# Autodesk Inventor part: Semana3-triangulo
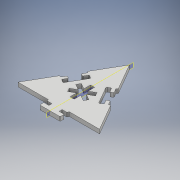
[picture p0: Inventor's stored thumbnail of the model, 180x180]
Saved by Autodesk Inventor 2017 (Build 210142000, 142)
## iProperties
Created: 2017-02
Part Number: Semana3-triangulo
Material: Generic
Document SubType Name: Modeling
Designer: diego
Density: 1 g/cm^3
Appearance: Default
Gdimension: 60.000 mm
garganta: 7.500 mm
d2: 3.750 mm
gargantah: 3.500 mm
espesor: 3.000 mm
d6: 0.00 deg
headw: 15.000 mm
headh: 3.020 mm
d36: 3.000 mm
d37: 0.00 deg
d42: 3.000 mm
d43: 0.00 deg
d44: 0.500 mm
d45: 30.00 deg
d47: 30.00 deg
d50: 15.040 mm
d51: 3.020 mm
d52: 3.000 ul
d54: 360.00 deg
d56: 3.000 mm
d57: 0.00 deg
d63: 90.00 deg
Author: diego
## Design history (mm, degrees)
sketch "Sketch1"
  geometry: L1 (0, 34.641)-(-30, -17.321); L2 (-30, -17.321)-(30, -17.321); L3 (30, -17.321)-(0, 34.641); L4 (-3.75, -17.321)-(-3.75, -20.821); L5 (3.75, -17.321)-(3.75, -20.821); L6 (-3.75, -20.821)-(-7.5, -20.821); L7 (-7.5, -20.821)-(-7.5, -23.841); L8 (-7.5, -23.841)-(7.5, -23.841); L9 (7.5, -23.841)-(7.5, -20.821); L10 (7.5, -20.821)-(3.75, -20.821); L11 (-3.75, -17.321)-(-3.75, -13.821); L12 (3.75, -17.321)-(3.75, -13.821); L13 (-3.75, -13.821)-(-7.5, -13.821); L14 (-7.5, -13.821)-(-7.5, -10.801); L15 (-7.5, -10.801)-(7.5, -10.801); L16 (7.5, -10.801)-(7.5, -13.821); L17 (7.5, -13.821)-(3.75, -13.821); L18 (-30, -17.321)-(15, 8.66); L19 (30, -17.321)-(-15, 8.66); L20 (0, 34.641)-(0, -17.321); L21 (3.75, -17.321)-(-3.75, -17.321); L22 (-7.5, -17.321)-(7.5, -17.321); L23 (7.5, -17.321)-(7.5, -18.571); L24 (7.5, -18.571)-(-7.5, -18.571); L25 (-7.5, -18.571)-(-7.5, -17.321); L26 (-7.5, -16.071)-(-7.5, -17.321); L27 (7.5, -16.071)-(-7.5, -16.071); L28 (7.5, -17.321)-(7.5, -16.071); L29 (17.667, 1.54)-(18.75, 2.165); L30 (11.25, 15.155)-(10.167, 14.53); L31 (18.75, 2.165)-(11.25, 15.155); L32 (16.875, 5.413)-(13.844, 3.663); L33 (13.125, 11.908)-(10.094, 10.158); L34 (10.167, 14.53)-(17.667, 1.54); L35 (8.219, 13.405)-(10.094, 10.158); L36 (5.604, 11.895)-(8.219, 13.405); L37 (13.104, -1.095)-(5.604, 11.895); L38 (15.719, 0.415)-(13.104, -1.095); L39 (13.844, 3.663)-(15.719, 0.415); L40 (-10.167, 14.53)-(-11.25, 15.155); L41 (-18.75, 2.165)-(-17.667, 1.54); L42 (-11.25, 15.155)-(-18.75, 2.165); L43 (-13.125, 11.908)-(-10.094, 10.158); L44 (-16.875, 5.413)-(-13.844, 3.663); L45 (-17.667, 1.54)-(-10.167, 14.53); L46 (-15.719, 0.415)-(-13.844, 3.663); L47 (-13.104, -1.095)-(-15.719, 0.415); L48 (-5.604, 11.895)-(-13.104, -1.095); L49 (-8.219, 13.405)-(-5.604, 11.895); L50 (-10.094, 10.158)-(-8.219, 13.405); L51 (13.125, 11.908)-(16.875, 5.413); L52 (18.75, 2.165)-(11.25, 15.155); L53 (10.167, 14.53)-(17.667, 1.54); L54 (11.25, 15.155)-(10.167, 14.53); L55 (17.667, 1.54)-(18.75, 2.165); L56 (16.875, 5.413)-(13.844, 3.663); L57 (13.125, 11.908)-(10.094, 10.158); L58 (8.219, 13.405)-(10.094, 10.158); L59 (5.604, 11.895)-(8.219, 13.405); L60 (13.104, -1.095)-(5.604, 11.895); L61 (15.719, 0.415)-(13.104, -1.095); L62 (13.844, 3.663)-(15.719, 0.415); L63 (-16.875, 5.413)-(-13.125, 11.908); L64 (-11.25, 15.155)-(-18.75, 2.165)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; 2 further points
  constraints: 148 end point, 11 point on line, 8 symmetric about line, 5 perpendicular, 4 equal length, 3 horizontal, 3 midpoint, 3 vertical, 2 collinear, 2 parallel, 2 vertical alignment, 1 coincident, 143 other
  dimensions: "Gdimension" = 60 distance of L1.end L2.end; "garganta" = 7.5 distance between parallel lines of L4 L5; "d2" = 3.75 distance from line of L4 L20.end (= 0.5 x garganta); "gargantah" = 3.5 distance of L4.start L4.end (computed from espesor); "headw" = 15 distance of L7.end L8.end (= 2 x garganta); "headh" = 3.02 distance between parallel lines of L6 L8 (computed from espesor); "d76" = 1.25 distance of L24.end L22.start; "d79" = 360 deg dimension on point (0, 0) L26.start (derived); "d83" = 360 deg dimension on point (0, 0) L5.start (derived)
extrude "Extrusion1" new body sketch "Sketch1" taper "d6" = 0 deg; stored distance "espesor" = 3
extrude "Extrusion5" join sketch "Sketch1" stored distance "d36" = 3; taper "d37" = 0 deg
extrude "Extrusion6" cut sketch "Sketch1" stored distance "d42" = 3; taper "d43" = 0 deg
fillet "Fillet2" dims "d44" = 0.5
sketch "Sketch6"
  geometry: L1 (-30, -17.321)-(-8, -17.321) reference; L2 (30, -17.321)-(19, 1.732) reference; L3 (-19, 1.732)-(-30, -17.321) reference; L4 (-30, -17.321)-(15, 8.66); L5 (0, 34.641)-(0, -17.321); L6 (30, -17.321)-(-15, 8.66); L7 (-30, -17.321)-(7.5, -17.321) reference; L8 (0, 34.641)-(-30, -17.321); L9 (-30, -17.321)-(30, -17.321); L10 (0, 34.641)-(30, -17.321); L11 (-5.758, -5.068)-(7.268, 2.452); L12 (7.268, 2.452)-(5.758, 5.068); L13 (5.758, 5.068)-(-7.268, -2.452); L14 (-7.268, -2.452)-(-5.758, -5.068); L15 (-5.758, -5.068)-(5.758, 5.068); L16 (7.268, 2.452)-(-7.268, -2.452); L17 (-7.268, 2.452)-(5.758, -5.068); L18 (5.758, -5.068)-(7.268, -2.452); L19 (7.268, -2.452)-(-5.758, 5.068); L20 (-5.758, 5.068)-(-7.268, 2.452); L21 (1.51, -7.52)-(1.51, 7.52); L22 (1.51, 7.52)-(-1.51, 7.52); L23 (-1.51, 7.52)-(-1.51, -7.52); L24 (-1.51, -7.52)-(1.51, -7.52); L25 (-3.75, -19.071)-(-3.75, -20.321) reference; L26 (3.75, -20.321)-(3.75, -19.071) reference; L27 (-4.25, -20.821)-(-7, -20.821) reference; L28 (-7.5, -21.321)-(-7.5, -23.341) reference; L29 (-7, -23.841)-(7, -23.841) reference; L30 (7.5, -23.341)-(7.5, -21.321) reference; L31 (7, -20.821)-(4.25, -20.821) reference; L32 (-7.5, -17.821)-(-7.5, -18.071) reference; L33 (4.25, -18.571)-(7, -18.571) reference; L34 (7.5, -18.071)-(7.5, -17.821) reference; L35 (18.317, 1.915)-(18.1, 1.79) reference; L36 (11.792, 11.716)-(10.417, 14.097) reference; L37 (15.359, 4.538)-(14.277, 3.913) reference; L38 (14.094, 3.23)-(15.469, 0.848) reference; L39 (15.286, 0.165)-(13.537, -0.845) reference; L40 (12.854, -0.662)-(5.854, 11.462) reference; L41 (6.037, 12.145)-(7.786, 13.155) reference; L42 (8.469, 12.972)-(9.844, 10.591) reference; L43 (10.527, 10.408)-(11.609, 11.033) reference; L44 (10.6, 14.78)-(10.817, 14.905) reference; L45 (-10.817, 14.905)-(-10.6, 14.78) reference; L46 (-10.417, 14.097)-(-11.792, 11.716) reference; L47 (-11.609, 11.033)-(-10.527, 10.408) reference; L48 (-9.844, 10.591)-(-8.469, 12.972) reference; L49 (-7.786, 13.155)-(-6.037, 12.145) reference; L50 (-5.854, 11.462)-(-12.854, -0.662) reference; L51 (-13.537, -0.845)-(-15.286, 0.165) reference; L52 (-15.469, 0.848)-(-14.094, 3.23) reference; L53 (-14.277, 3.913)-(-15.359, 4.538) reference; L54 (-18.1, 1.79)-(-18.317, 1.915) reference; L55 (11, 15.588)-(0, 34.641) reference; L56 (0, 34.641)-(-11, 15.588) reference; L57 (-16.042, 4.355)-(-17.417, 1.973) reference; L58 (-7, -18.571)-(-4.25, -18.571) reference; L59 (8, -17.321)-(30, -17.321) reference; L60 (17.417, 1.973)-(16.042, 4.355) reference; A1 r 0.5 centre (-4.25, -20.321) between (-4.25, -20.821) and (-3.75, -20.321) reference; A2 r 0.5 centre (-7, -21.321) between (-7, -20.821) and (-7.5, -21.321) reference; A3 r 0.5 centre (-7, -23.341) between (-7.5, -23.341) and (-7, -23.841) reference; A4 r 0.5 centre (7, -23.341) between (7, -23.841) and (7.5, -23.341) reference; A5 r 0.5 centre (7, -21.321) between (7.5, -21.321) and (7, -20.821) reference; A6 r 0.5 centre (4.25, -20.321) between (3.75, -20.321) and (4.25, -20.821) reference; A7 r 0.5 centre (10.277, 10.841) between (9.844, 10.591) and (10.527, 10.408) reference; A8 r 0.5 centre (11.359, 11.466) between (11.609, 11.033) and (11.792, 11.716) reference; A9 r 0.5 centre (10.85, 14.347) between (10.6, 14.78) and (10.417, 14.097) reference; A10 r 0.5 centre (10.567, 15.338) between (10.817, 14.905) and (11, 15.588) reference; A11 r 0.5 centre (-10.567, 15.338) between (-11, 15.588) and (-10.817, 14.905) reference; A12 r 0.5 centre (-10.85, 14.347) between (-10.417, 14.097) and (-10.6, 14.78) reference; A13 r 0.5 centre (-11.359, 11.466) between (-11.792, 11.716) and (-11.609, 11.033) reference; A14 r 0.5 centre (-10.277, 10.841) between (-10.527, 10.408) and (-9.844, 10.591) reference; A15 r 0.5 centre (-8.036, 12.722) between (-7.786, 13.155) and (-8.469, 12.972) reference; A16 r 0.5 centre (-6.287, 11.712) between (-5.854, 11.462) and (-6.037, 12.145) reference; A17 r 0.5 centre (-13.287, -0.412) between (-13.537, -0.845) and (-12.854, -0.662) reference; A18 r 0.5 centre (-15.036, 0.598) between (-15.469, 0.848) and (-15.286, 0.165) reference; A19 r 0.5 centre (-14.527, 3.48) between (-14.094, 3.23) and (-14.277, 3.913) reference; A20 r 0.5 centre (-15.609, 4.105) between (-15.359, 4.538) and (-16.042, 4.355) reference; A21 r 0.5 centre (-17.85, 2.223) between (-18.1, 1.79) and (-17.417, 1.973) reference; A22 r 0.5 centre (-18.567, 1.482) between (-18.317, 1.915) and (-19, 1.732) reference; A23 r 0.5 centre (-8, -17.821) between (-7.5, -17.821) and (-8, -17.321) reference; A24 r 0.5 centre (-7, -18.071) between (-7.5, -18.071) and (-7, -18.571) reference; A25 r 0.5 centre (-4.25, -19.071) between (-3.75, -19.071) and (-4.25, -18.571) reference; A26 r 0.5 centre (4.25, -19.071) between (4.25, -18.571) and (3.75, -19.071) reference; A27 r 0.5 centre (7, -18.071) between (7, -18.571) and (7.5, -18.071) reference; A28 r 0.5 centre (8, -17.821) between (8, -17.321) and (7.5, -17.821) reference; A29 r 0.5 centre (18.567, 1.482) between (19, 1.732) and (18.317, 1.915) reference; A30 r 0.5 centre (17.85, 2.223) between (17.417, 1.973) and (18.1, 1.79) reference; A31 r 0.5 centre (15.609, 4.105) between (16.042, 4.355) and (15.359, 4.538) reference; A32 r 0.5 centre (14.527, 3.48) between (14.277, 3.913) and (14.094, 3.23) reference; A33 r 0.5 centre (15.036, 0.598) between (15.286, 0.165) and (15.469, 0.848) reference; A34 r 0.5 centre (13.287, -0.412) between (12.854, -0.662) and (13.537, -0.845) reference; A35 r 0.5 centre (6.287, 11.712) between (6.037, 12.145) and (5.854, 11.462) reference; A36 r 0.5 centre (8.036, 12.722) between (8.469, 12.972) and (7.786, 13.155) reference; 6 further points; 2 other entities
  constraints: 40 end point, 5 midpoint, 3 parallel, 1 coincident, 1 perpendicular, 28 other
  dimensions: "d45" = 30 deg angle of L3 L5; "d47" = 30 deg angle of L1 L6; "d50" = 15.04 distance of L12.end L13.end (computed from headw); "d51" = 3.02 distance of L13.end L11.start (computed from espesor); "d54" = 360 deg dimension on point (0, 0) L12.end (derived)
extrude "Extrusion7" cut sketch "Sketch6" distance "d56" = 3; taper "d57" = 0 deg
workplane "Work Plane1"
body "Solid1"
node "Projected Loop2"
other parameters: "d52" = 3, "d63" = 90 deg
